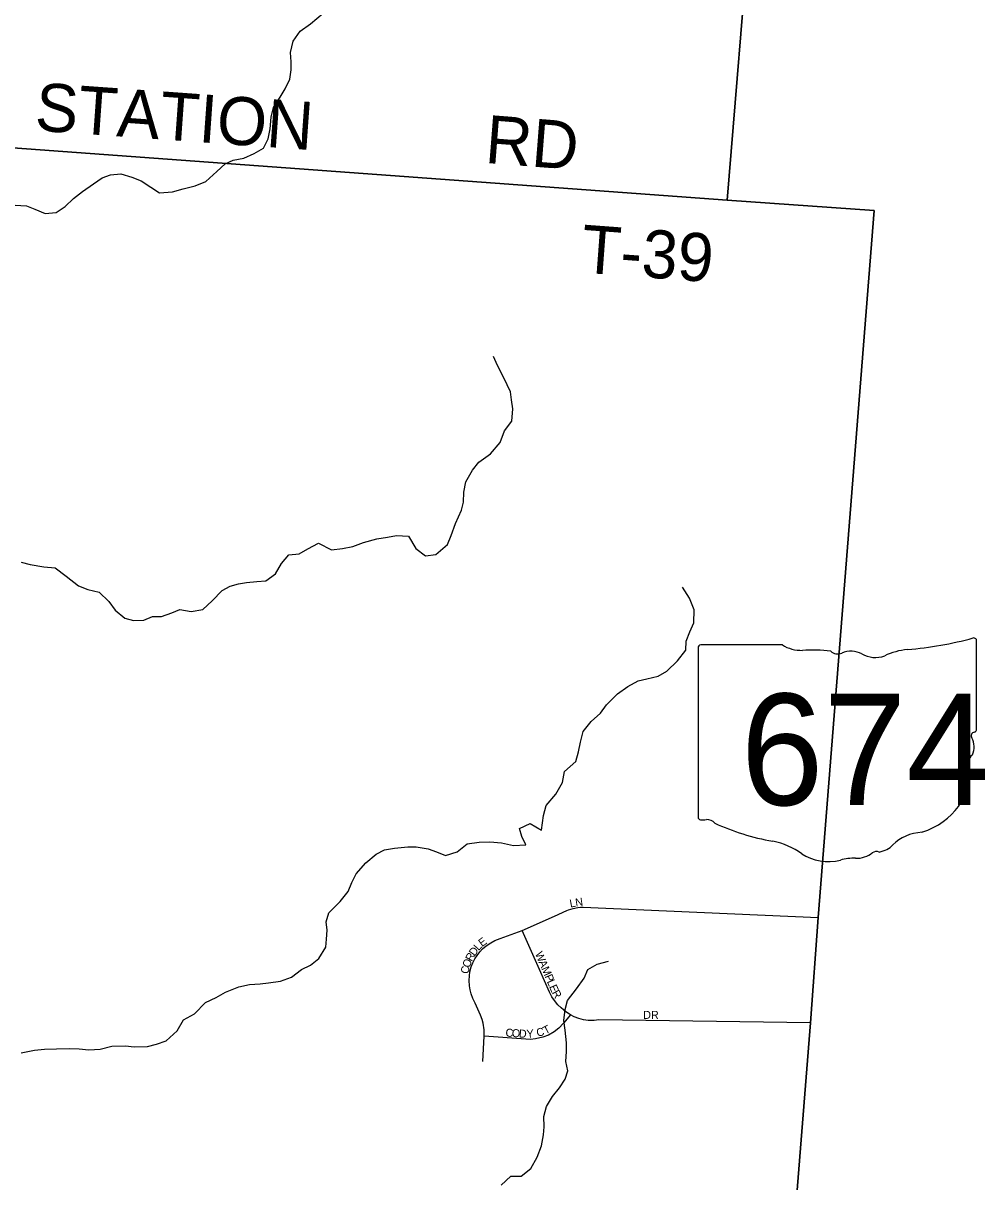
# Model space of a CAD drawing. Extents: x 1643459 to 2064572, y 425441 to 780708.
# Drawn here: x 1869026 to 1875035, y 594862 to 602101 of the extents above; entities that cross this region are included whole.
import ezdxf

# ---------------------------------------------------------------- set-up
doc = ezdxf.new("R2010")
doc.units = 0
for name, color, linetype in [('GM_X_City_Street', 7, 'Continuous'), ('GM_X_County', 7, 'Continuous'), ('GM_X_Interstate_Route', 7, 'Continuous'), ('GM_X_Major_River', 7, 'Continuous'), ('GM_X_Major_River_Text', 7, 'Continuous'), ('GM_X_Minor_River', 7, 'Continuous'), ('GM_X_Township', 7, 'Continuous'), ('GM_X_US_Route', 7, 'Continuous'), ('PM_P_Cells', 7, 'Continuous'), ('RD_X_Text', 7, 'Continuous'), ('ST_Details', 7, 'Continuous')]:
    doc.layers.add(name, color=color, linetype=linetype)

msp = doc.modelspace()

# ---------------------------------------------------------------- linework, layer by layer
at = {"layer": 'GM_X_City_Street'}
for points in [[(1874127.7, 610670.8), (1874002, 608977.1), (1873900.5, 607668.7), (1873820.8, 606443.6), (1873797.3, 606115.1), (1873746.1, 605342.8), (1873657.2, 604071.9), (1873574.2, 602927.5), (1873572.1, 602862.2), (1873573.5, 602796.9), (1873424.2, 600995.3), (1868960.6, 601322.8), (1866649.2, 601470.4), (1863982.7, 601657.3), (1860985.5, 601834), (1857189.7, 602061.2), (1851890.3, 602316.9), (1849050.7, 602434.2)], [(1857189.7, 602061.2), (1860985.5, 601834), (1863982.7, 601657.3), (1866649.2, 601470.4), (1868960.6, 601322.8), (1873424.2, 600995.3), (1874343.7, 600929.7), (1873993.6, 596512.5), (1873944.4, 595854.7), (1873837.4, 594497.5), (1873832.6, 594463.2), (1873804.1, 594079), (1873789.2, 593877.9), (1873731.7, 593076.8), (1873716.7, 592943.7), (1873711.2, 592838.6), (1873557, 590896.5), (1873465.3, 589684.5), (1873078.1, 584937.7)]]:
    msp.add_lwpolyline(points, dxfattribs=at)
at = {"layer": 'GM_X_County'}
for points in [[(1871899, 595613.1), (1871907.2, 595770.9), (1871907.2, 595811.2), (1871901, 595852.1), (1871894.2, 595876.4), (1871884, 595902.8), (1871850.6, 595977.7), (1871835.5, 596006.9), (1871824.2, 596037), (1871817.8, 596061.8), (1871813.7, 596087), (1871811.9, 596119.3), (1871813.7, 596149.4), (1871817.7, 596174.3), (1871825.8, 596204.8), (1871836.1, 596231), (1871847.8, 596254.1), (1871861.7, 596276.1), (1871879.3, 596298.7), (1871896.9, 596317.2), (1871919.1, 596336.2), (1871948.1, 596355.8), (1871973.5, 596368.9), (1872005.4, 596381), (1872143.9, 596432.1), (1872344.9, 596521.6), (1872423.5, 596556.5), (1872433.4, 596560.7), (1872461.6, 596570.1), (1872492.3, 596576.1), (1872508.5, 596577.7), (1872525.2, 596578.2), (1873993.6, 596512.5)], [(1873944.3, 595854.7), (1872623.7, 595873.2), (1872592.7, 595870), (1872556.9, 595870.6), (1872526.4, 595874.9), (1872497.6, 595882.3), (1872467.7, 595893.6), (1872446, 595904.8), (1872439.1, 595908.4), (1872415.7, 595924), (1872386.9, 595948.6), (1872367.4, 595967.4), (1872345.6, 595993.9), (1872330, 596017.8), (1872315.3, 596047.3), (1872252.2, 596188.9), (1872143.9, 596432.1)], [(1872446, 595904.8), (1872402.2, 595852.7), (1872373.7, 595822.8), (1872342.7, 595798.5), (1872308.8, 595779.1), (1872273.7, 595765), (1872227.5, 595754.4), (1872195.5, 595751.8), (1872166.6, 595752.7), (1871907.2, 595770.9)]]:
    msp.add_lwpolyline(points, dxfattribs=at)
at = {"layer": 'GM_X_Interstate_Route'}
msp.add_lwpolyline([(1873078.1, 584937.7), (1873465.3, 589684.5), (1873557, 590896.5), (1873711.2, 592838.6), (1873716.7, 592943.7), (1873731.7, 593076.8), (1873789.2, 593877.9), (1873804.1, 594079), (1873832.6, 594463.2), (1873837.4, 594497.5), (1873944.4, 595854.7), (1873993.6, 596512.5), (1874343.7, 600929.7), (1873424.2, 600995.3), (1873573.5, 602796.9), (1873572.1, 602862.2), (1873574.2, 602927.5), (1873657.2, 604071.9), (1873746.1, 605342.8), (1873797.3, 606115.1), (1873820.8, 606443.6), (1873900.5, 607668.7), (1874002, 608977.1), (1874127.7, 610670.8)], dxfattribs=at)
at = {"layer": 'GM_X_Major_River_Text'}
for points in [[(1873393.6, 600997.5), (1868960.6, 601322.7)], [(1874343.7, 600929.7), (1873424.2, 600995.3), (1873393.6, 600997.5)]]:
    msp.add_lwpolyline(points, dxfattribs=at)
at = {"layer": 'GM_X_Minor_River'}
msp.add_lwpolyline([(1874127.7, 610670.8), (1874002, 608977.1), (1873900.5, 607668.7), (1873820.8, 606443.6), (1873797.3, 606115.1), (1873746.1, 605342.8), (1873657.2, 604071.9), (1873574.2, 602927.5), (1873572.1, 602862.2), (1873573.5, 602796.9), (1873424.2, 600995.3), (1874343.7, 600929.7), (1873993.6, 596512.5), (1873944.4, 595854.7), (1873837.4, 594497.5), (1873832.6, 594463.2), (1873804.1, 594079), (1873789.2, 593877.9), (1873731.7, 593076.8), (1873716.7, 592943.7), (1873711.2, 592838.6), (1873557, 590896.5), (1873465.3, 589684.5), (1873078.1, 584937.7)], dxfattribs=at)
at = {"layer": 'GM_X_US_Route'}
for points in [[(1869339.7, 601005.7), (1869396.1, 601049.3), (1869464.6, 601096.8), (1869518.9, 601134.4), (1869571.1, 601154), (1869637.1, 601159.4), (1869704.9, 601138.7), (1869762.7, 601116), (1869824.3, 601075.3), (1869877.9, 601040.7), (1869958, 601048), (1870026.1, 601065.4), (1870100.3, 601084.7), (1870166.5, 601112.2), (1870235.1, 601173.7), (1870287.5, 601221.3), (1870337.7, 601244.9), (1870403.8, 601258.3), (1870470.1, 601285.8), (1870528.4, 601319.3), (1870556.9, 601379.2), (1870569.5, 601441.3), (1870576.2, 601513.4), (1870590.7, 601573.5), (1870631.3, 601639.3), (1870663.8, 601691.1), (1870692.4, 601751), (1870700.9, 601809.1), (1870699.4, 601859.3), (1870695.9, 601917.5), (1870712.6, 601987.5), (1870757.1, 602051.3), (1870821.6, 602096.8), (1870900.2, 602164.2)], [(1868975.4, 600963.1), (1869047.4, 600960.4), (1869099.2, 600937.8), (1869162.9, 600911.1), (1869233, 600918.5), (1869287.3, 600956.1), (1869339.7, 601005.7)], [(1869154.3, 598704.9), (1869226.2, 598698.2), (1869293.7, 598645.4), (1869371.1, 598584.4), (1869430.9, 598561.8), (1869500.7, 598545.1), (1869560.2, 598488.4), (1869601.7, 598433.8), (1869661.2, 598383.1), (1869715, 598368.6), (1869779, 598370), (1869833.2, 598393.5), (1869891.2, 598393), (1869955.4, 598416.4), (1870005.6, 598438), (1870075.5, 598425.3), (1870147.6, 598436.7), (1870206.1, 598492.2), (1870268.6, 598555.8), (1870318.9, 598583.4), (1870371, 598597), (1870421.1, 598606.5), (1870485.1, 598611.9), (1870541.2, 598617.4), (1870603.5, 598660.9), (1870640.1, 598724.8), (1870686.6, 598778.5), (1870750.7, 598785.9), (1870805, 598817.5), (1870871.3, 598851), (1870952.9, 598810.1), (1871020.9, 598819.4), (1871085, 598830.9), (1871153.2, 598856.3), (1871235.4, 598879.6), (1871301.5, 598889), (1871357.6, 598900.5), (1871433.5, 598895.7), (1871478.8, 598819.1), (1871540.4, 598772.4), (1871604.4, 598781.8), (1871677, 598843.3), (1871699.5, 598899.2), (1871728.2, 598975.2), (1871765, 599059.1), (1871777.4, 599109.1), (1871780, 599171.2), (1871792.6, 599235.3), (1871833.3, 599307.1), (1871873.7, 599358.9), (1871946.2, 599410.3), (1872006.8, 599480), (1872033.5, 599553.9), (1872080.1, 599613.7), (1872084.8, 599691.8), (1872077.3, 599748.1), (1872069.8, 599798.3), (1872028.6, 599884.9), (1871989.3, 599961.5), (1871963.9, 600017.9)], [(1869012.6, 598734.3), (1869070.5, 598719.7), (1869154.3, 598704.9)], [(1869858.3, 595721.6), (1869918.5, 595743.1), (1869989, 595804.6), (1870027.7, 595874.4), (1870096, 595911.8), (1870164.7, 595981.4), (1870230.9, 596012.9), (1870289.2, 596046.4), (1870373.5, 596079.7), (1870439.6, 596095.1), (1870507.7, 596098.5), (1870559.7, 596104), (1870633.8, 596115.3), (1870702, 596140.8), (1870764.4, 596188.3), (1870820.7, 596215.8), (1870873.1, 596257.4), (1870917.7, 596327.2), (1870920.2, 596377.3), (1870924.7, 596433.5), (1870919.2, 596485.7), (1870935.7, 596541.7), (1871006.3, 596613.2), (1871056.9, 596674.9), (1871079.4, 596730.9), (1871105.9, 596786.8), (1871166.5, 596854.4), (1871231, 596909.9), (1871283.3, 596935.5), (1871345.4, 596947), (1871429.4, 596954.2), (1871481.4, 596955.7), (1871557.3, 596942.9), (1871609.1, 596924.4), (1871664.8, 596899.8), (1871737, 596923.2), (1871799.5, 596972.7), (1871875.6, 596984), (1871941.6, 596985.4), (1872015.5, 596978.7), (1872089.3, 596963.9), (1872167.3, 596967.2), (1872141.8, 597019.6), (1872126.3, 597069.9), (1872194.6, 597101.3), (1872264.2, 597058.5), (1872277, 597150.7), (1872293.6, 597212.7), (1872354.3, 597284.3), (1872394.9, 597356.2), (1872407.6, 597426.2), (1872478.1, 597487.7), (1872494.7, 597547.8), (1872509.2, 597607.8), (1872525.9, 597675.8), (1872574.4, 597737.5), (1872632.9, 597789.1), (1872671.4, 597840.9), (1872740, 597910.5), (1872804.4, 597956), (1872868.7, 597991.5), (1872922.8, 598005), (1872993, 598020.4), (1873047.3, 598052), (1873113.8, 598117.5), (1873166.4, 598183.2), (1873169, 598239.3), (1873191.5, 598297.3), (1873216, 598355.2), (1873218.8, 598435.4), (1873189.5, 598507.9), (1873146.1, 598576.5)], [(1872013.5, 594840.5), (1872072, 594896.1), (1872138, 594897.5), (1872198.5, 594945.1), (1872237.1, 595014.9), (1872263.8, 595086.9), (1872276.4, 595154.9), (1872280.9, 595205), (1872279.5, 595269.2), (1872296.1, 595333.3), (1872332.6, 595395.1), (1872377.1, 595448.8), (1872411.6, 595502.7), (1872428.1, 595554.6), (1872416.6, 595612.9), (1872421.2, 595675), (1872419.7, 595731.2), (1872412.5, 595809.5), (1872405, 595869.8), (1872411.7, 595937.9), (1872426.2, 595993.9), (1872482.9, 596067.6), (1872531.5, 596133.3), (1872554, 596187.3), (1872612.3, 596220.8), (1872682.4, 596240.2)], [(1869014, 595667.4), (1869096.2, 595684.7), (1869158.2, 595690.1), (1869234.2, 595693.4), (1869316.2, 595694.7), (1869376.2, 595692.1), (1869436.1, 595685.5), (1869506.1, 595690.8), (1869580.3, 595710.2), (1869664.3, 595711.4), (1869720.2, 595704.8), (1869802.2, 595708.1), (1869858.3, 595721.6)]]:
    msp.add_lwpolyline(points, dxfattribs=at)
at = {"layer": 'RD_X_Text'}
msp.add_lwpolyline([(1873837.4, 594497.5), (1873944.3, 595854.7), (1873993.6, 596512.5), (1874343.7, 600929.7)], dxfattribs=at)
at = {"layer": 'ST_Details'}
for p, q in [((1874983.2, 597689.3), (1874983.2, 598242)), ((1873243, 598197.6), (1873243, 597141)), ((1873769.8, 598215.8), (1873260.2, 598215.8)), ((1874983.1, 597689.4), (1874983.2, 597689.3))]:
    msp.add_line(p, q, dxfattribs=at)
for centre, major_axis, start_param, end_param in [((1874363.4, 599656.4), (1845.5, 0), 4.814394, 5.042369), ((1874963.9, 598244.3), (19.4, 0), 6.141152, 7.989035), ((1873263, 598199.9), (20.2, 0), 1.712693, 3.28349), ((1873891.2, 598338.5), (195.5, 0), 4.042523, 4.731795), ((1873956, 597622.6), (702, 0), 1.404758, 1.657858), ((1874115.4, 598205.4), (56.4, 0), 3.836095, 5.185415), ((1874198.2, 598083.2), (117.3, 0), 0.950623, 2.079405), ((1874598.7, 597893.1), (371.3, 0), 1.699011, 2.107814), ((1874349.6, 598250.7), (141.1, 0), 4.081561, 5.145723), ((1874978.8, 597648.7), (30, 0), 1.883978, 3.671073), ((1874962.6, 597687.1), (20.7, 0), 5.05454, 6.418171), ((1874788, 597578.8), (180, 0), 5.934695, 6.695948), ((1875052.6, 597457.9), (130.9, 0), 2.387724, 3.262537), ((1874466.7, 597387.6), (461.6, 0), 5.101752, 6.440018), ((1873263.2, 597138.7), (20.3, 0), 3.00124, 4.508301), ((1873266.2, 597246.8), (155.2, 0), 4.665946, 4.897461), ((1873298, 597080), (56, 0), 0.519207, 1.627899), ((1874004.6, 598029.4), (1332.7, 0), 4.195997, 4.488961), ((1874661.4, 596844.3), (252.8, 0), 1.647645, 2.488434), ((1873607.3, 596666.3), (417, 0), 0.823519, 1.323587), ((1874341.1, 597038.6), (149.1, 0), 4.937069, 5.64225), ((1874058.3, 597074.8), (264.6, 0), 4.026481, 4.996735), ((1874211.1, 596709.5), (217.4, 0), 1.495662, 1.94098), ((1874230.5, 596995.7), (141, 0), 4.691044, 5.507374), ((1874358, 596893.3), (39.7, 0), 1.147584, 2.315152)]:
    msp.add_ellipse(centre, major_axis=major_axis, ratio=0.8, start_param=start_param, end_param=end_param, dxfattribs=at)

# ---------------------------------------------------------------- texts
at = {"layer": 'GM_X_Major_River'}
for s, rotation, p in [('STATION', 355.92541, (1869093.8, 601431)), ('RD', 355.52573, (1871906.2, 601228.4)), ('T-39', 355.76331, (1872505.3, 600543.1))]:
    msp.add_text(s, height=300, rotation=rotation, dxfattribs=at).set_placement(p)
at = {"layer": 'GM_X_Township'}
for s, rotation, p in [('L', 10.74723, (1872445, 596574.8)), ('N', 8.53509, (1872479.1, 596581.3)), ('E', 36.85897, (1871893.1, 596327.3)), ('R', 61.52326, (1871828.9, 596234.7)), ('D', 54.21844, (1871846.9, 596268.1)), ('L', 48.47991, (1871871.8, 596302.8)), ('W', 293.18756, (1872222.6, 596287.4)), ('C', 80.4099, (1871808.2, 596158.6)), ('O', 69.35952, (1871814.1, 596195.2)), ('A', 293.18138, (1872245.1, 596234.8)), ('M', 293.17193, (1872262.4, 596194.4)), ('P', 293.18846, (1872283.2, 596145.8)), ('L', 293.19142, (1872297.1, 596113.4)), ('E', 293.19142, (1872310.9, 596081.1)), ('R', 299.34812, (1872327.4, 596043.4)), ('DR', 0.00001, (1872900.2, 595879.8)), ('C', 356.13585, (1872038.5, 595769.8)), ('O', 356.12776, (1872078, 595767.1)), ('D', 356.45734, (1872122.2, 595764.1)), ('Y', 3.72742, (1872173, 595761.4)), ('C', 13.0308, (1872238.7, 595768)), ('T', 26.7853, (1872289.5, 595781.3))]:
    msp.add_text(s, height=50, rotation=rotation, dxfattribs=at).set_placement(p)
at = {"layer": 'PM_P_Cells'}
for s in ['s', 'r']:
    msp.add_text(s, height=1, dxfattribs=at).set_placement((1874093.6, 597599.1))
msp.add_text('674', height=1, rotation=0.00001, dxfattribs=at).set_placement((1873740.6, 597526.3))
at = {"layer": 'ST_Details'}
msp.add_text('674', height=696.1, dxfattribs=at).set_placement((1873508.8, 597215.5))

doc.saveas('drawing.dxf')
